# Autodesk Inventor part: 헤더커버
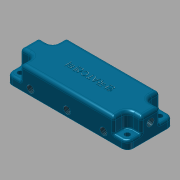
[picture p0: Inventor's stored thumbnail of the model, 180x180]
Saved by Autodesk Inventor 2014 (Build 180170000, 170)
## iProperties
Created: 2015-11
Part Number: 헤더커버
Material: 알루미늄 6061
Document SubType Name: Modeling
Designer: mduedu
Density: 2.71 g/cm^3
Appearance: 하늘색 짙음
Mass: 171.77 g
Surface Area: 160.864 cm^2
Volume: 63.3839 cm^3
Author: mduedu
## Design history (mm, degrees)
sketch "스케치1"
  geometry: L1 (52.5, 20)-(-52.5, 20); L2 (-52.5, 20)-(-52.5, -20); L3 (-52.5, -20)-(52.5, -20); L4 (52.5, -20)-(52.5, 20); L5 (52.5, 20)-(-52.5, -20); L6 (-52.5, 20)-(52.5, -20); 1 further point
  constraints: 12 end point, 2 midpoint, 2 parallel, 1 horizontal, 1 perpendicular
  dimensions: "d0" = 105 distance of L3.end L2.end; "d1" = 40 distance of L2.end L1.end
extrude "돌출1" new body sketch "스케치1" distance "d2" = 20; taper "d3" = 0 deg
sketch "스케치2"
  geometry: L1 (-52.5, -20)-(-52.5, 20) reference; L2 (-52.5, 20)-(52.5, 20) reference; L3 (52.5, 20)-(52.5, -20) reference; L4 (52.5, -20)-(-52.5, -20) reference; L5 (-52.5, 20)-(-40.5, 20); L6 (-40.5, 20)-(-40.5, 8); L7 (-40.5, 8)-(-52.5, 8); L8 (-52.5, 8)-(-52.5, 20); L9 (52.5, 20)-(40.5, 20); L10 (40.5, 20)-(40.5, 8); L11 (40.5, 8)-(52.5, 8); L12 (52.5, 8)-(52.5, 20); L13 (52.5, -20)-(40.5, -20); L14 (40.5, -20)-(40.5, -8); L15 (40.5, -8)-(52.5, -8); L16 (52.5, -8)-(52.5, -20); L17 (-52.5, -20)-(-40.5, -20); L18 (-40.5, -20)-(-40.5, -8); L19 (-40.5, -8)-(-52.5, -8); L20 (-52.5, -8)-(-52.5, -20); 1 further point
  constraints: 32 end point, 8 parallel, 6 equal length, 4 horizontal, 4 perpendicular
  dimensions: "d4" = 12 distance of L6.end L7.end; "d5" = 12 distance of L5.end L6.end
extrude "돌출2" cut sketch "스케치2" distance "d6" = 13; taper "d7" = 0 deg
fillet "모깎기1" dims "d8" = 5
fillet "모깎기2" dims "d9" = 1
fillet "모깎기3" dims "d10" = 5
fillet "모깎기4" dims "d11" = 2
fillet "모깎기5" dims "d12" = 3
sketch "스케치3"
  geometry: L1 (-46.5, -14)-(46.5, -14); L2 (46.5, -14)-(46.5, 14); L3 (46.5, 14)-(-46.5, 14); L4 (-46.5, 14)-(-46.5, -14); L5 (-46.5, -14)-(46.5, 14); L6 (46.5, -14)-(-46.5, 14); L7 (47.5, 20)-(-47.5, 20) reference; L8 (52.5, -15)-(52.5, 15) reference; 5 further points
  constraints: 12 end point, 4 coincident, 2 midpoint, 2 parallel, 1 horizontal, 1 perpendicular
  dimensions: "d13" = 6 distance between parallel lines of L3 L7; "d14" = 6 distance between parallel lines of L2 L8
hole "구멍1" sketch "스케치3" at (-46.5, 14), (46.5, 14), (46.5, -14), (-46.5, -14) diameter "d15" = 4.5; stored, may be unused: countersink angle "d19" = 90 deg, drill point angle "d21" = 118 deg; dims "d16" = 6, "d17" = 4, "d18" = 2, "d20" = 8
sketch "스케치4"
  geometry: L1 (47.5, -20)-(-47.5, -20) reference; L2 (52.5, 15)-(52.5, -15) reference; L3 (-47.5, 20)-(47.5, 20) reference; L4 (-52.5, -15)-(-52.5, 15) reference; L5 (-52.5, 0)-(52.5, 0); C1 r 12.25 at (0, 0); C2 r 2.25 at (46.5, 14) reference; C3 r 2.25 at (-46.5, -14) reference; C4 r 2.25 at (46.5, -14) reference; C5 r 2.25 at (-46.5, 14) reference; C6 r 12.25 at (-32, 0); C7 r 12.25 at (32, 0); A1 r 5 centre (-47.5, -15) between (-52.5, -15) and (-47.5, -20) reference; A2 r 5 centre (47.5, -15) between (47.5, -20) and (52.5, -15) reference; A3 r 5 centre (47.5, 15) between (52.5, 15) and (47.5, 20) reference; A4 r 5 centre (-47.5, 15) between (-47.5, 20) and (-52.5, 15) reference; 1 further point
  constraints: 3 centre point, 2 end point, 2 midpoint, 2 point on line, 1 coincident
  dimensions: "d22" = 24.5 diameter of C1; "d23" = 24.5 diameter of C7 (= d22); "d24" = 24.5 diameter of C6 (= d22); "d25" = 32 distance of point (0, 0) C6.centre; "d26" = 32 distance of C7.centre point (0, 0) (= d25)
extrude "돌출3" cut sketch "스케치4" distance "d27" = 8; taper "d28" = 0 deg
fillet "모깎기6" dims "d29" = 5
sketch "스케치5"
  geometry: L1 (-52.5, 12)-(-47.119, 12); L2 (-40.191, 8)-(-37.635, 3.574); L3 (-52.5, 17)-(-52.5, 8) reference; L4 (-47.5, 0)-(-52.5, 0) reference; L5 (37.5, 20)-(-37.5, 20) reference; L6 (0, 0)-(0, 20); L7 (52.5, 12)-(47.119, 12); L8 (40.191, 8)-(37.635, 3.574); A1 r 8 centre (-47.119, 4) between (-40.191, 8) and (-47.119, 12); A2 r 8 centre (47.119, 4) between (47.119, 12) and (40.191, 8); 1 further point
  constraints: 10 end point, 5 symmetric about line, 4 point on circle, 3 point on line, 2 centre point, 2 tangent, 1 horizontal, 1 midpoint, 1 other
  dimensions: "d30" = 10 distance of L1.start point (-42.5, 12); "d32" = 120 deg angle of L2 L1; "d34" = 12 distance between parallel lines of L1 L4; "d35" = 8 radius of A1
sketch "스케치6"
  geometry: L1 (20, -5)-(20, 5) reference; L2 (8, -20)-(17, -20) reference; L3 (12, -20)-(12, -14.619); L4 (8, -7.691)-(3.81, -5.272); L5 (0, -20)-(0, -15) reference; A1 r 8 centre (4, -14.619) between (12, -14.619) and (8, -7.691); 2 further points
  constraints: 4 end point, 3 point on line, 2 point on circle, 2 tangent, 1 centre point, 1 perpendicular
  dimensions: "d36" = 10 distance of L3.start point (12, -10); "d38" = 12 distance between parallel lines of L3 L5; "d39" = 120 deg angle of L3 L4; "d40" = 8 radius of A1
node "작업점1"
node "작업점2"
node "작업점3"
hole "구멍2" diameter "d43" = 5.944; stored, may be unused: countersink angle "d49" = 90 deg, drill point angle "d51" = 0 deg; dims "d41" = 10, "d42" = 10, "d44" = 6.886, "d45" = 0.62479, "d46" = 5.959, "d47" = 4, "d48" = 2, "d50" = 6.9
hole "구멍3" diameter "d54" = 5.944; stored, may be unused: countersink angle "d60" = 90 deg, drill point angle "d62" = 0 deg; dims "d52" = 10, "d53" = 10, "d55" = 6.886, "d56" = 0.62479, "d57" = 5.959, "d58" = 4, "d59" = 2, "d61" = 6.9
hole "구멍4" diameter "d65" = 5.944; stored, may be unused: countersink angle "d71" = 90 deg, drill point angle "d73" = 0 deg; dims "d63" = 10, "d64" = 10, "d66" = 6.886, "d67" = 0.62479, "d68" = 5.959, "d69" = 4, "d70" = 2, "d72" = 6.9
sketch "스케치7"
  geometry: C1 r 2.972 at (15, 12) reference; 1 further point
sketch "스케치8"
  geometry: C1 r 2.972 at (15, 12) reference; 1 further point
sketch "스케치9"
  geometry: C1 r 2.972 at (47.5, 12) reference; 1 further point
feature "스윕1" dims "d74" = 0
feature "스윕2" dims "d75" = 0
feature "스윕3" dims "d76" = 0
sketch "스케치10"
  geometry: L1 (0, 0)-(95, 0) reference; L2 (22.75, 8)-(8.768, 8) reference; L3 (54.75, 8)-(40.25, 8) reference; L4 (86.232, 8)-(72.25, 8) reference; L5 (15.759, 8)-(15.759, 0); L6 (47.5, 8)-(47.5, 0); L7 (79.241, 8)-(79.241, 0); 5 further points
  constraints: 6 end point, 5 point on line, 3 midpoint, 2 horizontal alignment, 2 perpendicular, 1 parallel
  dimensions: "d77" = 5 distance from line of point (15.759, 5) L1
hole "구멍5" sketch "스케치10" at (15.759, 5), (47.5, 5), (79.241, 5) diameter "d78" = 5.944; stored, may be unused: countersink angle "d84" = 90 deg, drill point angle "d86" = 0 deg; dims "d79" = 6.886, "d80" = 0.62479, "d81" = 5.959, "d82" = 4, "d83" = 2, "d85" = 6.9
sketch "스케치11"
  geometry: C1 r 2.972 at (0, 0) reference; C2 r 2.972 at (31.741, 0) reference; C3 r 2.972 at (63.482, 0) reference; 1 further point
extrude "돌출4" cut sketch "스케치11" distance "d87" = 8; taper "d88" = 0 deg
sketch "스케치12"
  geometry: 2 further points
  constraints: 1 coincident, 1 other
feature "엠보싱1" sketch "스케치12" dims "d0" = 105, "d1" = 40, "d4" = 12, "d5" = 12, "d89" = 0.5, "d90" = 0
node "솔리드1"
node "투영된 루프1"
node "절단 모서리 투영1"
